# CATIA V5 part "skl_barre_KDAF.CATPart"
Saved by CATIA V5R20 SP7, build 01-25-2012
Part number: skl_barre_KDAF
Publications: "Point.K", "Point.F", "Droite.1", "Droite.2", "Droite.3", "Droite.4", "Droite.5"
Bounding box of the stored display mesh (mm): x -150 to 150, y 30 to 30, z -20 to 0
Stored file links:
  D:\IFMA\COURS\2A\projet balance IAO\catia\skl_barre_KDAF.CATPart
  D:\IFMA\COURS\2A\projet balance IAO\catia\Skl_projet_balance.CATProduct
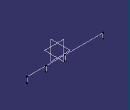
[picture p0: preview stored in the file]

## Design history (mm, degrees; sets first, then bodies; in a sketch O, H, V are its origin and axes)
External parameters (linked from other documents)
  External.L_barre = 150 mm
Set1
  Point1 "Point.D": linked copy from another document
  Point2 "Point.F": linked copy from another document
  Point3 "Point.K": linked copy from another document
  Point4 "Point.A": linked copy from another document
  Plane1 "Plan.KDAF": linked copy from another document
  Point5 "Point.G": linked copy from another document
Body1 (main body)
  Point6 "Point.K": stored without definition
  Point7 "Point.F": stored without definition
  Line1: type PtPt, FirstPoint Point3, SecondPoint Point2
  Line2: type PtDir, RefPoint Point1, Direction xy-plane, Start 0, End 20
  Line3: type PtDir, RefPoint Point2, Direction xy-plane, Start 0, End 20
  Line4: type PtDir, RefPoint Point3, Direction xy-plane, Start 0, End 20
  Line5: type PtDir, RefPoint Point4, Direction xy-plane, Start 0, End 20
